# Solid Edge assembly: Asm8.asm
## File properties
Author: Cadcim
Template: Iso Assembly.asm
Last saved by: Cadcim
Revision: 2
Application: Solid Edge
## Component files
cam.par
floorere.par
follower.par
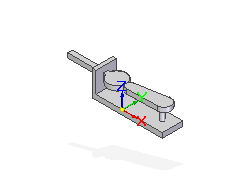
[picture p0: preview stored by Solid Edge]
